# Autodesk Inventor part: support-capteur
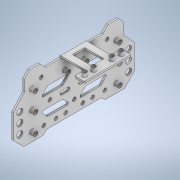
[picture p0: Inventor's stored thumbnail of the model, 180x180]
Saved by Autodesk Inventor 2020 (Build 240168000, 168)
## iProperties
Created: 2022-02
Part Number: support-capteur
Material: Générique
Document SubType Name: Modeling
Designer: bruno
Density: 1 g/cm^3
Appearance: Par défaut
Author: bruno
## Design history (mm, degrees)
sketch "Esquisse1"
  geometry: L1 (66.232, 46.839)-(46.199, 46.839); L2 (66.23, -52.161)-(46.2, -52.161); L3 (89.845, 25.399)-(89.845, 33.715); L4 (37.796, 38.782)-(37.796, 23.107); L5 (46.199, 46.839)-(37.796, 38.532); L6 (89.845, 25.399)-(85.193, 20.8); L7 (85.193, 20.8)-(85.193, -2.661); L8 (89.845, 33.715)-(85.193, 37.93); L9 (85.193, 37.93)-(76.064, 37.93); L10 (76.064, 37.93)-(66.232, 46.839); L11 (37.796, 23.107)-(40.701, 19.391); L12 (40.701, 19.391)-(40.701, -2.661); L13 (40.701, -2.661)-(50.092, -2.661); L14 (50.092, -2.661)-(85.193, -2.661); L15 (71.331, 18.786)-(71.331, 3.129); L16 (71.016, 19.515)-(66.917, 23.371); L17 (65.232, 7.141)-(65.232, 22.643); L18 (69.631, 2.414)-(65.532, 6.426); L19 (61.89, 7.414)-(61.89, 2.414); L20 (58.89, 7.414)-(58.89, 2.414); L21 (60.39, 17.308)-(60.39, 7.414); L22 (49.764, 19.515)-(53.863, 23.371); L23 (55.548, 7.141)-(55.548, 22.643); L24 (49.449, 18.786)-(49.449, 3.129); L25 (51.148, 2.414)-(55.247, 6.426); C1 r 1.5 at (79.831, 24.339); C2 r 2.5 at (64.046, 41.839); C3 r 2.5 at (56.046, 41.839); C4 r 2.5 at (48.046, 41.839); C5 r 1.5 at (60.39, 17.308); C6 r 1.5 at (44.701, 22.339); C7 r 1.5 at (44.701, 12.339); C8 r 1.5 at (44.701, 4.339); C9 r 1.5 at (60.39, 31.839); C10 r 1.5 at (75.4, 31.839); C11 r 1.5 at (44.89, 31.839); C12 r 1.5 at (75.193, 4.839); C13 r 1.5 at (50.831, -2.661); A1 r 1.5 centre (60.39, 7.414) between (61.89, 7.414) and (58.89, 7.414); A2 r 1 centre (70.331, 3.129) between (69.631, 2.414) and (71.331, 3.129); A3 r 1 centre (66.232, 7.141) between (65.232, 7.141) and (65.532, 6.426); A4 r 1 centre (66.232, 22.643) between (66.917, 23.371) and (65.232, 22.643); A5 r 1 centre (70.331, 18.786) between (71.331, 18.786) and (71.016, 19.515); A6 r 1.5 centre (60.39, 2.414) between (58.89, 2.414) and (61.89, 2.414); A7 r 1 centre (54.548, 22.643) between (55.548, 22.643) and (53.863, 23.371); A8 r 1 centre (50.449, 18.786) between (49.764, 19.515) and (49.449, 18.786); A9 r 1 centre (54.548, 7.141) between (55.247, 6.426) and (55.548, 7.141); A10 r 1 centre (50.449, 3.129) between (49.449, 3.129) and (51.148, 2.414); 3 further points
  constraints: 50 end point, 23 centre point, 20 point on circle, 12 symmetric about line, 10 tangent, 6 vertical, 3 horizontal, 3 parallel, 2 equal radius, 2 point on line, 1 perpendicular, 4 other
  dimensions: "d5" = 99 distance between parallel lines of L2 L1; "d8" = 52.04902 distance between parallel lines of L3 L4; "d16" = 49.5 distance between parallel lines of L1 L13; "d17" = 1 radius of A2 (derived); "d19" = 1 radius of A5 (derived); "d20" = 5 diameter of C2; "d21" = 5 diameter of C3; "d22" = 5 diameter of C4; "d23" = 3 dimension on C4 C3; "d24" = 8 distance of C2.centre C3.centre; "d25" = 5 distance from line of C2.centre L1; "d26" = 5 distance from line of L1 C3.centre; "d27" = 7.5 dimension on C4 L1; "d28" = 3 diameter of C10; "d29" = 3 diameter of C9; "d30" = 3 diameter of C11; "d31" = 15 distance from line of L1 C9.centre; "d32" = 15 distance from line of L1 C11.centre; "d33" = 15 distance from line of L1 C10.centre; "d34" = 3 diameter of C6; "d35" = 3 diameter of C7; "d36" = 3 diameter of C8; "d37" = 24.5 distance from line of C6.centre L1; "d38" = 4 distance from line of L12 C6.centre; "d39" = 4 distance from line of L12 C7.centre; "d40" = 4 distance from line of L12 C8.centre; "d41" = 10 distance of C7.centre C6.centre; "d42" = 8 distance of C8.centre C7.centre; "d43" = 3 diameter of C1; "d44" = 10 distance from line of C12.centre L7; "d45" = 3 diameter of C12; "d46" = 27 vertical distance of C12.centre C10.centre; "d47" = 3 diameter of C5; "d48" = 3 diameter of A6; "d49" = 3 diameter of A1; "d50" = 5 distance of A6.centre L21.end; "d52" = 3 diameter of C13; "d103" = 34.5 distance from line of L14 C10.centre (derived); "d104" = 27 distance from line of L14 C1.centre; "d105" = 29 horizontal distance of C13.centre C1.centre
extrude "Extrusion1" new body sketch "Esquisse1" distance "d53" = 1.5; taper "d54" = 0 deg
sketch "Esquisse2"
  geometry: C1 r 1.5 at (-31.839, 75.4) reference; C2 r 1.5 at (-31.839, 60.39) reference; C3 r 1.5 at (-31.839, 44.89) reference; C4 r 1.5 at (-4.839, 75.193) reference; C5 r 1.5 at (10.161, 75.193) reference; C6 r 1.5 at (37.161, 75.4) reference; C7 r 1.5 at (37.161, 60.39) reference; C8 r 1.5 at (37.161, 44.89) reference; C9 r 2 at (-31.839, 75.4); C10 r 1.5 at (-31.839, 60.39) reference; C11 r 2 at (-31.839, 60.39); C12 r 1.5 at (-31.839, 44.89) reference; C13 r 2 at (-31.839, 44.89); C14 r 1.5 at (-4.839, 75.193) reference; C15 r 2 at (-4.839, 75.193); 1 further point
  constraints: 4 centre point, 4 coincident
  dimensions: "d55" = 4 diameter of C9; "d56" = 4 diameter of C11; "d57" = 4 diameter of C13; "d58" = 4 diameter of C15
extrude "Extrusion2" join sketch "Esquisse2" distance "d59" = 3; taper "d60" = 0 deg
feature "Filetage1" dims "d61" = 4.5, "d62" = 0
feature "Filetage2" dims "d63" = 4.5, "d64" = 0
feature "Filetage3" dims "d65" = 4.5, "d66" = 0
feature "Filetage4" dims "d67" = 4.5, "d68" = 0
mirror "Symétrie2"
sketch "Esquisse3"
  geometry: L1 (0, 0)-(0, 46.922) reference; L2 (1.5, 0)-(1.5, 46.922) reference; L3 (0, 1.409)-(0, 45.513) reference; L4 (0, 12.961)-(20.5, 12.961); L5 (21, 12.961)-(21, 27.961); L6 (20.5, 33.961)-(0, 33.961); L7 (0, 33.961)-(0, 12.961); L8 (21.5, 4.461)-(28.5, 4.461); L9 (29, 4.961)-(29, 41.961); L10 (28.5, 42.461)-(21.5, 42.461); L11 (21, 12.461)-(21, 4.961); L12 (1.5, 1.409)-(1.5, 45.513) reference; L13 (1.5, 23.461)-(-9.009, 23.461); L14 (5.5, 18.461)-(20.5, 18.461); L15 (21, 18.961)-(21, 28.461); L16 (20.5, 28.461)-(5.5, 28.461); L17 (5, 27.961)-(5, 18.961); L18 (21, 41.961)-(21, 34.461); C1 r 1.5 at (25, 8.461); C2 r 1.5 at (25, 15.961); C3 r 1.5 at (25, 30.961); C4 r 1.5 at (25, 38.461); A1 r 0.5 centre (20.5, 12.461) between (21, 12.461) and (20.5, 12.961); A2 r 0.5 centre (5.5, 18.961) between (5, 18.961) and (5.5, 18.461); A3 r 0.5 centre (20.5, 18.961) between (20.5, 18.461) and (21, 18.961); A4 r 0.5 centre (20.5, 27.961) between (21, 27.961) and (20.5, 28.461); A5 r 0.5 centre (5.5, 27.961) between (5.5, 28.461) and (5, 27.961); A6 r 0.5 centre (20.5, 34.461) between (20.5, 33.961) and (21, 34.461); A7 r 0.5 centre (21.5, 41.961) between (21.5, 42.461) and (21, 41.961); A8 r 0.5 centre (28.5, 41.961) between (29, 41.961) and (28.5, 42.461); A9 r 0.5 centre (28.5, 4.961) between (28.5, 4.461) and (29, 4.961); A10 r 0.5 centre (21.5, 4.961) between (21, 4.961) and (21.5, 4.461); 10 further points
  constraints: 28 end point, 20 point on circle, 20 tangent, 18 point on line, 14 centre point, 8 equal radius, 6 parallel, 4 horizontal, 3 perpendicular, 2 symmetric about line, 1 midpoint, 1 vertical, 2 other
  dimensions: "d69" = 21 distance of L6.end point (21, 33.961); "d70" = 21 distance of point (21, 33.961) L5.start; "d71" = 8 distance of point (21, 42.461) point (29, 42.461); "d72" = 38 distance of point (29, 42.461) point (29, 4.461); "d73" = 10.5 distance between parallel lines of L6 L13; "d74" = 19 distance between parallel lines of L8 L13; "d75" = 10 distance between parallel lines of L16 L14; "d76" = 16 distance of point (5, 18.461) point (21, 18.461); "d77" = 5 distance between parallel lines of L13 L14; "d78" = 5 distance between parallel lines of L7 L17; "d79" = 0.5 radius of A1; "d80" = 0.5 radius of A6 (derived); "d81" = 3 diameter of C1; "d82" = 3 diameter of C2; "d83" = 7.5 distance from line of C2.centre L13; "d84" = 15 distance from line of L13 C1.centre
extrude "Extrusion3" join sketch "Esquisse3" distance "d85" = 1.5; taper "d86" = 0 deg
fillet "Congé1" dims "d87" = 1
sketch "Esquisse4"
  geometry: C1 r 1.5 at (25, 8.461) reference; C2 r 1.5 at (25, 15.961) reference; C3 r 1.5 at (25, 30.961) reference; C4 r 1.5 at (25, 38.461) reference; C5 r 2 at (25, 8.461); C6 r 1.5 at (25, 15.961) reference; C7 r 2 at (25, 15.961); C8 r 1.5 at (25, 30.961) reference; C9 r 2 at (25, 30.961); C10 r 2 at (25, 38.461); 1 further point
  constraints: 4 centre point, 4 coincident
  dimensions: "d88" = 4 diameter of C5; "d89" = 4 diameter of C7; "d90" = 4 diameter of C9; "d91" = 4 diameter of C10
extrude "Extrusion4" join sketch "Esquisse4" distance "d92" = 3; taper "d93" = 0 deg
feature "Filetage5" dims "d94" = 4.5, "d95" = 0
feature "Filetage6" dims "d96" = 4.5, "d97" = 0
feature "Filetage7" dims "d98" = 4.5, "d99" = 0
feature "Filetage8" dims "d100" = 4.5, "d101" = 0
node "Solide1"
